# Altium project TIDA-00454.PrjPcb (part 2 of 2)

## Sheet Pg8. Analog Outputs.SchDoc
size 431 x 279 mm; Date: Not shown in title block; ApprovedBy: Not shown in title block; CheckedBy: Not shown in title block; Author: Not shown in title block; CompanyName: Not shown in title block; Engineer: Not shown in title block; Organization: Not shown in title block; Address1: Not shown in title block; Address2: Not shown in title block; Address3: Not shown in title block; Address4: Not shown in title block; DocumentNumber: 7; Revision: Use project parameter SCH_Rev; SheetNumber: 8; SheetTotal: 10; PageSetup: Record=PageOptions¦CenterHorizontal=True¦CenterVertical=True¦PrintScale=1.00¦XCorrection=1.00¦YCorrection=1.00¦PrintKind=0¦BorderSize=5000000¦LeftOffset=0¦BottomOffset=0¦Orientation=2¦PaperLength=1000¦PaperWidth=1000¦Scale=100¦PaperSource=15¦PrintQuality=600¦MediaType=1¦DitherType=10¦PaperKind=Letter¦PrintScaleMode=1
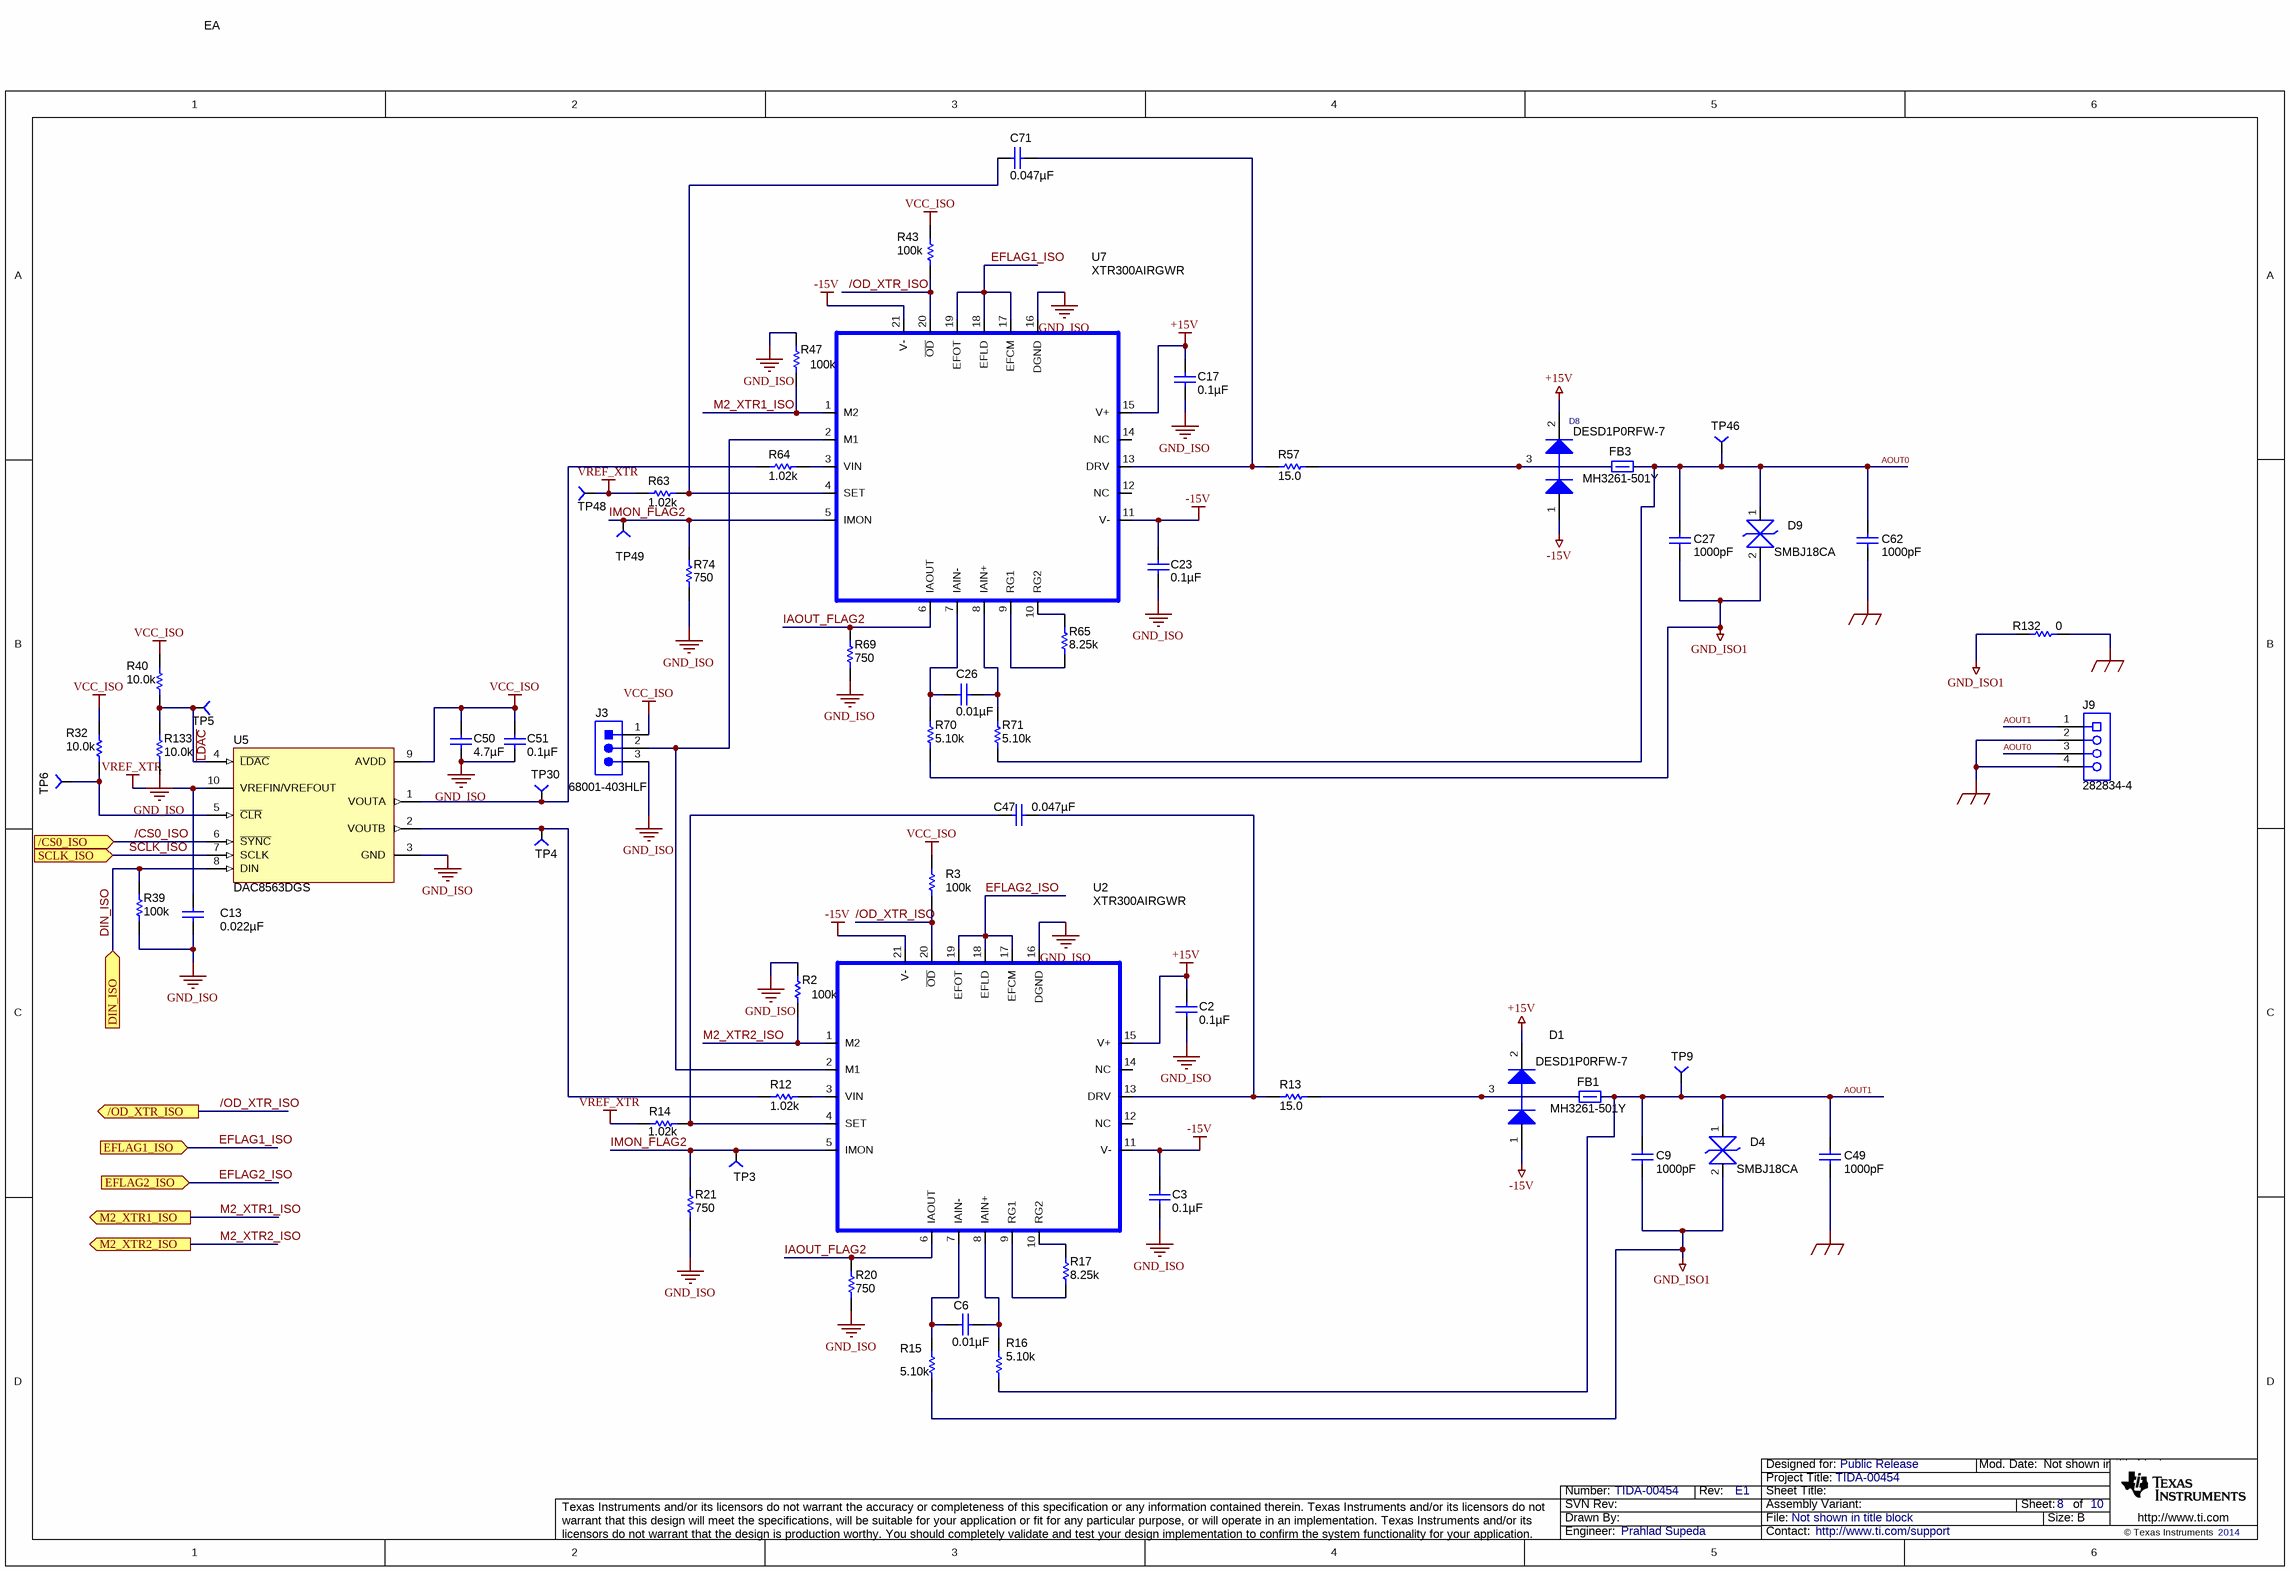
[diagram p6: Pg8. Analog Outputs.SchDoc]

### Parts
C2  ValueDisplayed: 0.1µF  [0603]  (hidden comment: GRM188R71H104KA93D)
C3  ValueDisplayed: 0.1µF  [0603]  (hidden comment: GRM188R71H104KA93D)
C6  ValueDisplayed: 0.01µF  [0603]  (hidden comment: C0603C103J5RACTU)
C9  value 1000pF  [1206]  (hidden comment: 202R18W102KV4E)
C13  ValueDisplayed: 0.022µF  [0603]  (hidden comment: C0603C223K4RACTU)
C17  ValueDisplayed: 0.1µF  [0603]  (hidden comment: GRM188R71H104KA93D)
C23  ValueDisplayed: 0.1µF  [0603]  (hidden comment: GRM188R71H104KA93D)
C26  ValueDisplayed: 0.01µF  [0603]  (hidden comment: C0603C103J5RACTU)
C27  value 1000pF  [1206]  (hidden comment: 202R18W102KV4E)
C47  ValueDisplayed: 0.047µF  [0603]  (hidden comment: C1608X7R1H473K)
C49  value 1000pF  [1206]  (hidden comment: 202R18W102KV4E)
C50  ValueDisplayed: 4.7µF  [1206]  (hidden comment: C3216X7R1C475K)
C51  ValueDisplayed: 0.1µF  [0603]  (hidden comment: GRM188R71H104KA93D)
C62  value 1000pF  [1206]  (hidden comment: 202R18W102KV4E)
C71  ValueDisplayed: 0.047µF  [0603]  (hidden comment: C1608X7R1H473K)
D1  DESD1P0RFW-7  [SOT-323]
D4  SMBJ18CA  [DIO_SMB_BIAAAA]
D8  DESD1P0RFW-7  [SOT-323]
D9  SMBJ18CA  [DIO_SMB_BIAAAA]
FB1  MH3261-501Y  [1210]
FB3  MH3261-501Y  [1210]
J3  68001-403HLF  [HDR1X3]
J9  282834-4  [TEC_282834-4]
R2  value 100k  [0603]  (hidden comment: CRCW0603100KFKEA)
R3  value 100k  [0603]  (hidden comment: CRCW0603100KFKEA)
R12  value 1.02k  [0603]  (hidden comment: RT0603BRD071K02L)
R13  value 15.0  [0603]  (hidden comment: CRCW060315R0FKEA)
R14  value 1.02k  [0603]  (hidden comment: RT0603BRD071K02L)
R15  value 5.10k  [0603]  (hidden comment: CRCW06032K00FKEA)
R16  value 5.10k  [0603]  (hidden comment: CRCW06032K00FKEA)
R17  value 8.25k  [0603]  (hidden comment: RG1608P-8251-B-T5)
R20  value 750  [0603]  (hidden comment: CRCW0603750RFKEA)
R21  value 750  [0603]  (hidden comment: CRCW0603750RFKEA)
R32  value 10.0k  [0603]  (hidden comment: CRCW060310K0FKEA)
R39  value 100k  [0603]  (hidden comment: CRCW0603100KFKEA)
R40  value 10.0k  [0603]  (hidden comment: CRCW060310K0FKEA)
R43  value 100k  [0603]  (hidden comment: CRCW0603100KFKEA)
R47  value 100k  [0603]  (hidden comment: CRCW0603100KFKEA)
R57  value 15.0  [0603]  (hidden comment: CRCW060315R0FKEA)
R63  value 1.02k  [0603]  (hidden comment: RT0603BRD071K02L)
R64  value 1.02k  [0603]  (hidden comment: RT0603BRD071K02L)
R65  value 8.25k  [0603]  (hidden comment: RG1608P-8251-B-T5)
R69  value 750  [0603]  (hidden comment: CRCW0603750RFKEA)
R70  value 5.10k  [0603]  (hidden comment: CRCW06032K00FKEA)
R71  value 5.10k  [0603]  (hidden comment: CRCW06032K00FKEA)
R74  value 750  [0603]  (hidden comment: CRCW0603750RFKEA)
R132  value 0  [0603]  (hidden comment: RC0603JR-070RL)
R133  value 10.0k  [0603]  (hidden comment: CRCW060310K0FKEA)
TP3  TP-040_RND  [TP-040_RND]  (value not drawn)
TP4  TP-040_RND  [TP-040_RND]  (value not drawn)
TP5  TP-040_RND  [TP-040_RND]  (value not drawn)
TP6  TP-040_RND  [TP-040_RND]  (value not drawn)
TP9  TP-040_RND  [TP-040_RND]  (value not drawn)
TP30  TP-040_RND  [TP-040_RND]  (value not drawn)
TP46  TP-040_RND  [TP-040_RND]  (value not drawn)
TP48  TP-040_RND  [TP-040_RND]  (value not drawn)
TP49  TP-040_RND  [TP-040_RND]  (value not drawn)
U2  XTR300AIRGWR  [RGW20]
U5  DAC8563DGS  U/M: EA  [DGS0010A_N]
U7  XTR300AIRGWR  [RGW20]

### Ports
/CS0_ISO (in), /OD_XTR_ISO (out), DIN_ISO (in), EFLAG1_ISO (in), EFLAG2_ISO (in), M2_XTR1_ISO (out), M2_XTR2_ISO (out), SCLK_ISO (in)

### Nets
+15V: C2.1 C17.1 D1.2(K) D8.2(K) U2.15(V+) U7.15(V+)
-15V: C3.1 C23.1 D1.1(A) D8.1(A) U2.11(V-) U2.21(V-) U7.11(V-) U7.21(V-)
GND_EARTH: C49.2 C62.2 J9.2 J9.4 R132.2
GND_ISO: C2.2 C3.2 C13.2 C17.2 C23.2 C50.2 C51.2 J3.3 R2.2 R20.2 R21.1 R39.1 R47.2 R69.2 R74.1 R133.1 U2.16(DGND) U5.3(GND) U7.16(DGND)
GND_ISO1: C9.2 C27.2 D4.2 D9.2 R15.1 R70.1 R132.1
VCC_ISO: C50.1 C51.1 J3.1 R3.2 R32.2 R40.2 R43.2 U5.9(AVDD)
VREF_XTR: C13.1 R14.1 R63.1 TP48.1 U5.10(VREFIN/VREFOUT)
/CS0_ISO: U5.6(~{SYNC}) ; port /CS0_ISO
/OD_XTR_ISO: R3.1 R43.1 U2.20(~{OD}) U7.20(~{OD}) ; port /OD_XTR_ISO
~{LDAC}: R40.1 R133.2 TP5.1 U5.4(~{LDAC})
AOUT0: C27.1 C62.1 D9.1 FB3.2 J9.3 R71.1 TP46.1
AOUT1: C9.1 C49.1 D4.1 FB1.2 J9.1 R16.1 TP9.1
DIN_ISO: R39.2 U5.8(DIN) ; port DIN_ISO
EFLAG1_ISO: U7.17(EFCM) U7.18(EFLD) U7.19(EFOT) ; port EFLAG1_ISO
EFLAG2_ISO: U2.17(EFCM) U2.18(EFLD) U2.19(EFOT) ; port EFLAG2_ISO
IAOUT_FLAG2: R20.1 R69.1 U2.6(IAOUT) U7.6(IAOUT)
IMON_FLAG2: R21.2 R74.2 TP3.1 TP49.1 U2.5(IMON) U7.5(IMON)
M2_XTR1_ISO: R47.1 U7.1(M2) ; port M2_XTR1_ISO
M2_XTR2_ISO: R2.1 U2.1(M2) ; port M2_XTR2_ISO
SCLK_ISO: U5.7(SCLK) ; port SCLK_ISO
NetC6_1: C6.1 R16.2 U2.8(IAIN+)
NetC6_2: C6.2 R15.2 U2.7(IAIN-)
NetC26_1: C26.1 R71.2 U7.8(IAIN+)
NetC26_2: C26.2 R70.2 U7.7(IAIN-)
NetC47_1: C47.1 R13.1 U2.13(DRV)
NetC47_2: C47.2 R14.2 U2.4(SET)
NetC71_1: C71.1 R57.1 U7.13(DRV)
NetC71_2: C71.2 R63.2 U7.4(SET)
NetD1_3: D1.3(C) FB1.1 R13.2
NetD8_3: D8.3(C) FB3.1 R57.2
NetJ3_2: J3.2 U2.2(M1) U7.2(M1)
NetR12_1: R12.1 TP4.1 U5.2(VOUTB)
NetR12_2: R12.2 U2.3(VIN)
NetR17_1: R17.1 U2.9(RG1)
NetR17_2: R17.2 U2.10(RG2)
NetR32_1: R32.1 TP6.1 U5.5(~{CLR})
NetR64_1: R64.1 TP30.1 U5.1(VOUTA)
NetR64_2: R64.2 U7.3(VIN)
NetR65_1: R65.1 U7.9(RG1)
NetR65_2: R65.2 U7.10(RG2)

Not connected (* = marked no-connect by the designer): U2 12(NC) 14(NC); U7 12(NC) 14(NC)

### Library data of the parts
C2 C3 C17 C23 C51 = GRM188R71H104KA93D: CAP, CERM, 0.1uF, 50V, +/-10%, X7R, 0603; Manufacturer: MuRata; Polarized: N; CompType: Capacitor; U/M: EA; Cap_F: 0.0000001; Tolerance_%: 10; VDC_V: 50; TaMin_C: -55; TaMax_C: 125
C6 C26 = C0603C103J5RACTU: CAP, CERM, 0.01uF, 50V, +/-5%, X7R, 0603; Manufacturer: Kemet; Polarized: N; CompType: Capacitor; U/M: EA; Cap_F: 0.00000001; Tolerance_%: 5; Value1: Unknown; VDC_V: 50; TaMin_C: -55; TaMax_C: 125
C9 C27 C49 C62 = 202R18W102KV4E: CAP, CERM, 1000pF, 2KV 10% X7R 1206; Manufacturer: Johanson Dielectrics Inc; Polarized: N; CompType: Capacitor; Cap_F: 0.000000001; Tolerance_%: 0
C13 = C0603C223K4RACTU: CAP, CERM, 0.022uF, 16V, +/-10%, X7R, 0603; Manufacturer: Kemet; Polarized: N; CompType: Capacitor; U/M: EA; Cap_F: 0.000000022; Tolerance_%: 10; Value1: Unknown; VDC_V: 16; TaMin_C: -55; TaMax_C: 125
C47 C71 = C1608X7R1H473K: CAP, CERM, 0.047uF, 50V, +/-10%, X7R, 0603; Manufacturer: TDK; Polarized: N; CompType: Capacitor; U/M: EA; Cap_F: 0.000000047; Tolerance_%: 10; ESR_Ohm: 0.0234; Value1: 0.0234 ohm; VDC_V: 50; TaMin_C: -55; TaMax_C: 125
C50 = C3216X7R1C475K: CAP, CERM, 4.7uF, 16V, +/-10%, X7R, 1206; Manufacturer: TDK; Polarized: N; CompType: Capacitor; U/M: EA; Cap_F: 0.0000047; Tolerance_%: 10; ESR_Ohm: 0.0036; Value1: 0.0036 ohm; VDC_V: 16; IRMS_A: 2; TaMin_C: -55; TaMax_C: 125
D1 D8 = BAV99WT1G: Diode, P-N, 70V, 0.2A, SOT-323; Manufacturer: Diodes Inc
D4 D9 = SMBJ18CA: TVS 18 VOLT 600 WATT BI-DIR SMB; Manufacturer: Littelfuse Inc
FB1 FB3 = Ferrite_Bead: BEAD FERRITE 500 OHM 3.0A 3216; Manufacturer: Bourns Inc.; CompType: Resistor; U/M: EA
J3 = 009155003301006: 3 pin berger; Manufacturer: FCI; SymbolCreator: a0799628; CompType: Connector; U/M: EA
J9 = 282834-4: Receptacle, 100mil, 4X1 TH; Manufacturer: TE Connectivity; SymbolCreator: a0411947; U/M: EA
R2 R3 R39 R43 R47 = CRCW0603100KFKEA: RES, 100k ohm, 1%, 0.1W, 0603; Manufacturer: Vishay-Dale; CompType: Resistor; Res_ohm: 100000; Tolerance_%: 1; Power_W: 0.1; VDC_V: 75; TempCo: 100 ppm/C; EIA_Code: E96; U/M: EA
R12 R14 R63 R64 = RT0603BRD071K02L: RES, 1.02k ohm, 0.1%, 0.1W, 0603; Manufacturer: Yageo America; CompType: Resistor; Res_ohm: 1020; Value_Code: 1k02; Tolerance_%: 0.1; VDC_V: 75; TempCo: 25 ppm/C; EIA_Code: E192; U/M: EA
R13 R57 = CRCW080515R0FKEA: RES, 15.0 ohm, 1%, 0.125W, 0805; Manufacturer: Vishay-Dale; CompType: Resistor; Res_ohm: 15; Value_Code: 15R0; Tolerance_%: 1; Power_W: 0.125; VDC_V: 150; TempCo: 100 ppm/C; EIA_Code: E96; U/M: EA
R15 R16 R70 R71 = RC0603FR-075K1L: RES, 5.10k ohm, 1%, 0.1W, 0603; Manufacturer: Yageo America; CompType: Resistor; Res_ohm: 5100; Value_Code: 5k10; Tolerance_%: 1; Power_W: 0.1; VDC_V: 150; TempCo: 200 ppm/C; U/M: EA
R17 R65 = RG1608P-8251-B-T5: RES, 8.25k ohm, 0.1%, 0.1W, 0603; Manufacturer: Susumu Co Ltd; CompType: Resistor; Res_ohm: 8250; Value_Code: 8k25; Tolerance_%: 0.1; VDC_V: 75; TempCo: 25 ppm/C; EIA_Code: E192; U/M: EA
R20 R21 R69 R74 = CRCW0603750RFKEA: RES, 750 ohm, 1%, 0.1W, 0603; Manufacturer: Vishay-Dale; CompType: Resistor; Value_Code: 750R; Tolerance_%: 1; Power_W: 0.1; VDC_V: 75; TempCo: 100 ppm/C; EIA_Code: E96; U/M: EA
R32 R40 R133 = CRCW060310K0FKEA: RES, 10.0k ohm, 1%, 0.1W, 0603; Manufacturer: Vishay-Dale; CompType: Resistor; Res_ohm: 10000; Value_Code: 10k0; Tolerance_%: 1; Power_W: 0.1; VDC_V: 75; TempCo: 100 ppm/C; EIA_Code: E96; U/M: EA
R132 = RC0402JR-070RL: RES, 0 ohm,5%, 0.1W, 0603; Manufacturer: Yageo America; CompType: Resistor; Value_Code: 0000; Tolerance_%: 5; Power_W: 0.1; VDC_V: 50; TempCo: 200 ppm/C; EIA_Code: E24; U/M: EA
TP3-TP6 TP9 TP30 TP46 TP48 TP49 = TP-040_RND: Test Point, O.040 Hole; Manufacturer: STD; Value: STD
U2 U7 = XTR300AIRGWR: IC, Industrial Analog Current/Voltage Output Driver; Area: 72900; Note: Please confirm to Librarian when the part is officially released
U5 = DAC8563DGS: DUAL 16-/14-/12-BIT, ULTRALOW-GLITCH, LOW-POWER, BUFFERED, VOLTAGE-OUTPUT DAC WITH 2.5-V, 4-PPM/°C INTERNAL REFERENCE IN SMALL 3-MM ?3-MM SON, DGS0010A; Alternate Manufacturer: None; Manufacturer: Texas Instruments; SymbolCreator: a0411947; CompType: IC

## Sheet Pg9 Expansion Interface.SchDoc
size 431 x 279 mm; Date: Not shown in title block; ApprovedBy: Not shown in title block; CheckedBy: Not shown in title block; Author: Not shown in title block; CompanyName: Not shown in title block; Engineer: Not shown in title block; Organization: Not shown in title block; Address1: Not shown in title block; Address2: Not shown in title block; Address3: Not shown in title block; Address4: Not shown in title block; DocumentNumber: 7; Revision: Use project parameter SCH_Rev; SheetNumber: 9; SheetTotal: 10; PageSetup: Record=PageOptions¦CenterHorizontal=True¦CenterVertical=True¦PrintScale=1.00¦XCorrection=1.00¦YCorrection=1.00¦PrintKind=0¦BorderSize=5000000¦LeftOffset=0¦BottomOffset=0¦Orientation=2¦PaperLength=1000¦PaperWidth=1000¦Scale=100¦PaperSource=15¦PrintQuality=600¦MediaType=1¦DitherType=10¦PaperKind=Letter¦PrintScaleMode=1
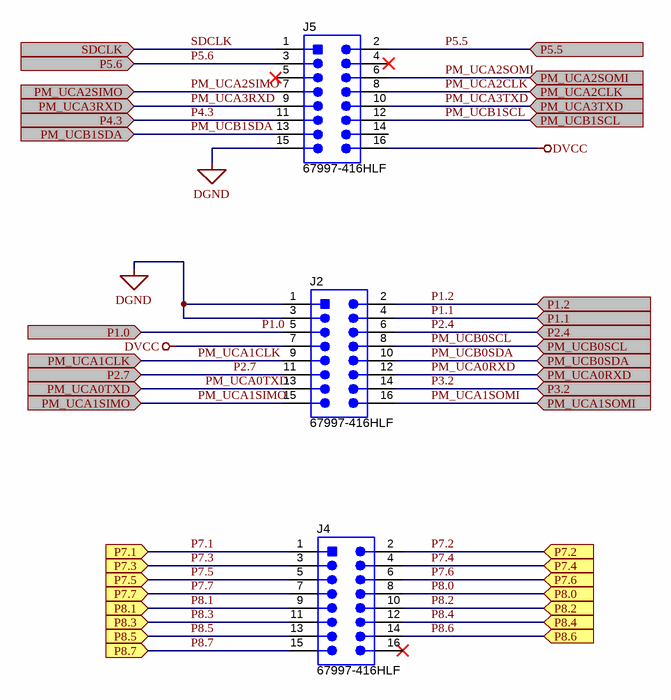
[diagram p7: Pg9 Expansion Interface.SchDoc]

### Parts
J2  67997-416HLF  [TSW-108-07-G-D]
J4  67997-416HLF  [TSW-108-07-G-D]
J5  67997-416HLF  [TSW-108-07-G-D]

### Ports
P1.0, P1.1, P1.2, P2.4, P2.7, P3.2, P4.3, P5.5, P5.6, P7.1, P7.2, P7.3, P7.4, P7.5, P7.6, P7.7, P8.0, P8.1, P8.2, P8.3, P8.4, P8.5, P8.6, P8.7, PM_UCA0RXD, PM_UCA0TXD, PM_UCA1CLK, PM_UCA1SIMO, PM_UCA1SOMI, PM_UCA2CLK, PM_UCA2SIMO, PM_UCA2SOMI, PM_UCA3RXD, PM_UCA3TXD, PM_UCB0SCL, PM_UCB0SDA, PM_UCB1SCL, PM_UCB1SDA, SDCLK

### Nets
DGND: J2.1 J2.3 J5.15
DVCC: J2.7 J5.16
P1.0: J2.5 ; port P1.0
P1.1: J2.4 ; port P1.1
P1.2: J2.2 ; port P1.2
P2.4: J2.6 ; port P2.4
P2.7: J2.11 ; port P2.7
P3.2: J2.14 ; port P3.2
P4.3: J5.11 ; port P4.3
P5.5: J5.2 ; port P5.5
P5.6: J5.3 ; port P5.6
P7.1: J4.1 ; port P7.1
P7.2: J4.2 ; port P7.2
P7.3: J4.3 ; port P7.3
P7.4: J4.4 ; port P7.4
P7.5: J4.5 ; port P7.5
P7.6: J4.6 ; port P7.6
P7.7: J4.7 ; port P7.7
P8.0: J4.8 ; port P8.0
P8.1: J4.9 ; port P8.1
P8.2: J4.10 ; port P8.2
P8.3: J4.11 ; port P8.3
P8.4: J4.12 ; port P8.4
P8.5: J4.13 ; port P8.5
P8.6: J4.14 ; port P8.6
P8.7: J4.15 ; port P8.7
PM_UCA0RXD: J2.12 ; port PM_UCA0RXD
PM_UCA0TXD: J2.13 ; port PM_UCA0TXD
PM_UCA1CLK: J2.9 ; port PM_UCA1CLK
PM_UCA1SIMO: J2.15 ; port PM_UCA1SIMO
PM_UCA1SOMI: J2.16 ; port PM_UCA1SOMI
PM_UCA2CLK: J5.8 ; port PM_UCA2CLK
PM_UCA2SIMO: J5.7 ; port PM_UCA2SIMO
PM_UCA2SOMI: J5.6 ; port PM_UCA2SOMI
PM_UCA3RXD: J5.9 ; port PM_UCA3RXD
PM_UCA3TXD: J5.10 ; port PM_UCA3TXD
PM_UCB0SCL: J2.8 ; port PM_UCB0SCL
PM_UCB0SDA: J2.10 ; port PM_UCB0SDA
PM_UCB1SCL: J5.12 ; port PM_UCB1SCL
PM_UCB1SDA: J5.13 ; port PM_UCB1SDA
SDCLK: J5.1 ; port SDCLK

Not connected (* = marked no-connect by the designer): J4 16*; J5 4* 5* 14

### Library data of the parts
J2 J4 J5 = PBC08DBAN: Header, 8x2, 100mil, TH; Manufacturer: FCI; SymbolCreator: a0412235; U/M: EA

## Sheet Pg10.HARDWARE - MISCELLANEOUS..SchDoc: Hardware - MIiscellaneous
size 431 x 279 mm; Date: Not shown in title block; ApprovedBy: Not shown in title block; CheckedBy: Not shown in title block; Author: Not shown in title block; CompanyName: Not shown in title block; Engineer: Not shown in title block; Organization: Not shown in title block; Address1: Not shown in title block; Address2: Not shown in title block; Address3: Not shown in title block; Address4: Not shown in title block; DocumentNumber: 8; Revision: Use project parameter SCH_Rev; SheetNumber: 10; SheetTotal: 10; PageSetup: Record=PageOptions¦CenterHorizontal=True¦CenterVertical=True¦PrintScale=1.00¦XCorrection=1.00¦YCorrection=1.00¦PrintKind=0¦BorderSize=5000000¦LeftOffset=0¦BottomOffset=0¦Orientation=2¦PaperLength=1000¦PaperWidth=1000¦Scale=100¦PaperSource=15¦PrintQuality=600¦MediaType=1¦DitherType=10¦PaperKind=Letter¦PrintScaleMode=1
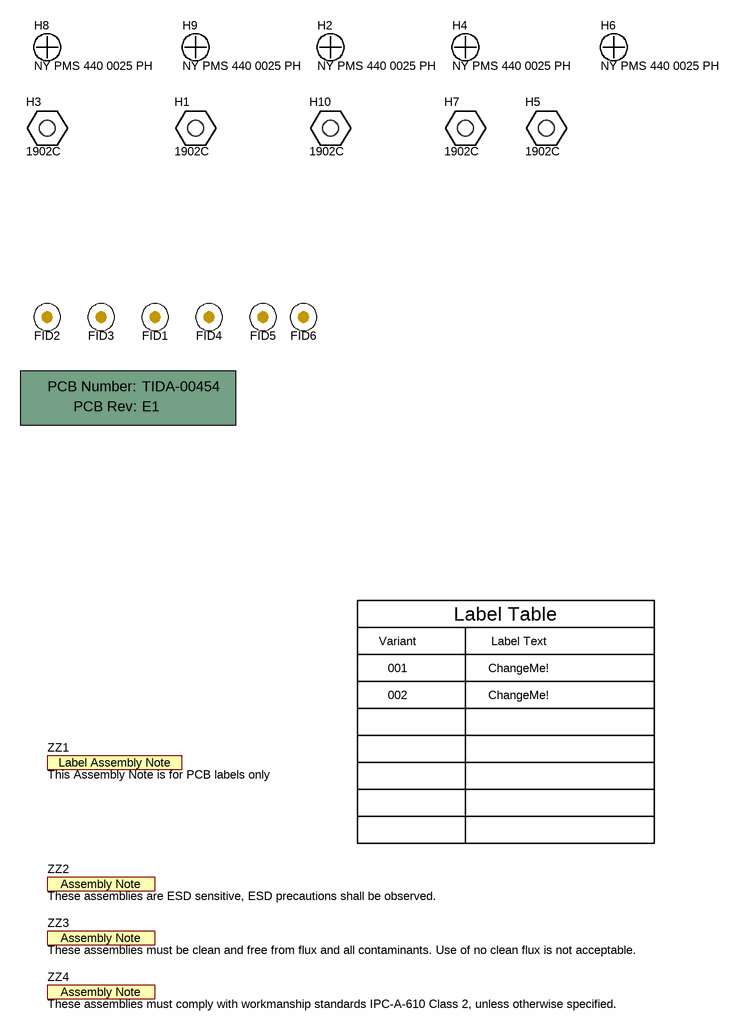
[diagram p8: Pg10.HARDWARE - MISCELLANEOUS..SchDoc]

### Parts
!PCB1  Printed Circuit Board  (value not drawn)  (mechanical)
FID1  Fiducial  [Fiducial10-20]  (value not drawn)
FID2  Fiducial  [Fiducial10-20]  (value not drawn)
FID3  Fiducial  [Fiducial10-20]  (value not drawn)
FID4  Fiducial  [Fiducial10-20]  (value not drawn)
FID5  Fiducial  [Fiducial10-20]  (value not drawn)
FID6  Fiducial  [Fiducial10-20]  (value not drawn)
H1  1902C  [Keystone_1902C]
H2  NY PMS 440 0025 PH  [NY PMS 440 0025 PH]
H3  1902C  [Keystone_1902C]
H4  NY PMS 440 0025 PH  [NY PMS 440 0025 PH]
H5  1902C  [Keystone_1902C]
H6  NY PMS 440 0025 PH  [NY PMS 440 0025 PH]
H7  1902C  [Keystone_1902C]
H8  NY PMS 440 0025 PH  [NY PMS 440 0025 PH]
H9  NY PMS 440 0025 PH  [NY PMS 440 0025 PH]
H10  1902C  [Keystone_1902C]
ZZ1  This Assembly Note is for PCB labels only  [AssemblyNoteLabel]  (no BOM)
ZZ2  These assemblies are ESD sensitive, ESD precautions shall be observed.  [AssemblyNote]  (no BOM)
ZZ3  These assemblies must be clean and free from flux and all contaminants. Use of no clean flux is not acceptable.  [AssemblyNote]  (no BOM)
ZZ4  These assemblies must comply with workmanship standards IPC-A-610 Class 2, unless otherwise specified.  [AssemblyNote]  (no BOM)

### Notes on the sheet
- Variant
- Label Table
- Label Text
- 001
- 002
- ChangeMe!

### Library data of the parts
!PCB1 = PCB: Manufacturer: Any; PartNumber: TIDA-00454; SymbolCreator: a0412235
FID1-FID6 = Fiducial: Fiducial mark.  There is nothing to buy or mount.; SymbolCreator: codlsc
H1 H3 H5 H7 H10 = 1902C: Standoff, Hex, 0.5"L #4-40 Nylon; Manufacturer: Keystone; CompType: Hardware
H2 H4 H6 H8 H9 = NY PMS 440 0025 PH: Machine Screw, Round, #4-40 x 1/4, Nylon, Philips panhead; Manufacturer: B&F Fastener Supply; CompType: Hardware; SymbolCreator: codlsc; U/M: EA
ZZ1 = AssemblyNoteLabel: SymbolCreator: a0412235
ZZ2-ZZ4 = AssemblyNote: SymbolCreator: codlsc

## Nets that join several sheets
+15V: Pg6.Isolated and Non Isolated Power Supply (9 pins), Pg8. Analog Outputs (6 pins)
-15V: Pg6.Isolated and Non Isolated Power Supply (C72.2 C74.2 D12.2 J14.2), Pg8. Analog Outputs (8 pins)
AGND: Pg3.MSP430F67791A+LED (U6.112 U6.120), Pg4. Relay Drivers+JTAG Interface +Decoupling Capacitors (8 pins), Pg5.Analog Front End - Current and Voltage (36 pins)
AVCC: Pg3.MSP430F67791A+LED (U6.121), Pg4. Relay Drivers+JTAG Interface +Decoupling Capacitors (C68.1 C69.1 FB4.2)
DGND: Pg3.MSP430F67791A+LED (14 pins), Pg4. Relay Drivers+JTAG Interface +Decoupling Capacitors (21 pins), Pg6.Isolated and Non Isolated Power Supply (10 pins), Pg7.Digital Isolators (7 pins), Pg9 Expansion Interface (J2.1 J2.3 J5.15)
DVCC: Pg3.MSP430F67791A+LED (7 pins), Pg4. Relay Drivers+JTAG Interface +Decoupling Capacitors (9 pins), Pg6.Isolated and Non Isolated Power Supply (5 pins), Pg7.Digital Isolators (16 pins), Pg9 Expansion Interface (J2.7 J5.16)
GND_ISO: Pg6.Isolated and Non Isolated Power Supply (17 pins), Pg7.Digital Isolators (7 pins), Pg8. Analog Outputs (19 pins)
GND_ISO1: Pg6.Isolated and Non Isolated Power Supply (R106.1 R107.1), Pg8. Analog Outputs (7 pins)
VASYS1: Pg3.MSP430F67791A+LED (U6.111 U6.122), Pg4. Relay Drivers+JTAG Interface +Decoupling Capacitors (C63.1 C65.1 C67.1 C70.1)
VCC_ISO: Pg6.Isolated and Non Isolated Power Supply (6 pins), Pg7.Digital Isolators (14 pins), Pg8. Analog Outputs (8 pins)
VREF: Pg3.MSP430F67791A+LED (U6.113), Pg4. Relay Drivers+JTAG Interface +Decoupling Capacitors (C64.1)
/CS0: Pg3.MSP430F67791A+LED (U6.35), Pg7.Digital Isolators (R22.1 U4.3)
/CS0_ISO: Pg7.Digital Isolators (R23.2 R37.1), Pg8. Analog Outputs (U5.6)
/OD_XTR: Pg3.MSP430F67791A+LED (U6.34), Pg7.Digital Isolators (R52.1 R53.2 U8.5)
/OD_XTR_ISO: Pg7.Digital Isolators (R56.1 R62.2), Pg8. Analog Outputs (R3.1 R43.1 U2.20 U7.20)
AUXVCC1: Pg3.MSP430F67791A+LED (U6.124), Pg4. Relay Drivers+JTAG Interface +Decoupling Capacitors (C54.1 C55.1 TP53.1)
AUXVCC2: Pg3.MSP430F67791A+LED (U6.123), Pg4. Relay Drivers+JTAG Interface +Decoupling Capacitors (C52.1 C53.1)
AUXVCC3: Pg3.MSP430F67791A+LED (R108.2 U6.3), Pg4. Relay Drivers+JTAG Interface +Decoupling Capacitors (C59.1 C60.1 TP52.1)
DIN_ISO: Pg7.Digital Isolators (R29.2 R30.1 R38.2), Pg8. Analog Outputs (R39.2 U5.8)
EFLAG1: Pg3.MSP430F67791A+LED (TP7.1 U6.26), Pg7.Digital Isolators (R27.1 U4.6)
EFLAG1_ISO: Pg7.Digital Isolators (R31.1 R50.2), Pg8. Analog Outputs (U7.17 U7.18 U7.19)
EFLAG2: Pg3.MSP430F67791A+LED (TP17.1 U6.27), Pg7.Digital Isolators (R60.1 U8.6)
EFLAG2_ISO: Pg7.Digital Isolators (R61.1 R67.2), Pg8. Analog Outputs (U2.17 U2.18 U2.19)
I1+: Pg3.MSP430F67791A+LED (U6.103), Pg5.Analog Front End - Current and Voltage (C18.1 C21.1 R51.1)
I1-: Pg3.MSP430F67791A+LED (U6.104), Pg5.Analog Front End - Current and Voltage (C21.2 C24.2 R66.1)
I2+: Pg3.MSP430F67791A+LED (U6.105), Pg5.Analog Front End - Current and Voltage (C28.1 C33.1 R75.1)
I2-: Pg3.MSP430F67791A+LED (U6.106), Pg5.Analog Front End - Current and Voltage (C28.2 C34.2 R76.1)
I3+: Pg3.MSP430F67791A+LED (U6.107), Pg5.Analog Front End - Current and Voltage (C29.1 C35.1 R77.1)
I3-: Pg3.MSP430F67791A+LED (U6.108), Pg5.Analog Front End - Current and Voltage (C29.2 C36.2 R78.1)
M2_XTR1: Pg3.MSP430F67791A+LED (U6.28), Pg7.Digital Isolators (R45.1 U8.3)
M2_XTR1_ISO: Pg7.Digital Isolators (R54.2 R68.1), Pg8. Analog Outputs (R47.1 U7.1)
M2_XTR2: Pg3.MSP430F67791A+LED (U6.29), Pg7.Digital Isolators (R48.1 U8.4)
M2_XTR2_ISO: Pg7.Digital Isolators (R49.1 R55.2), Pg8. Analog Outputs (R2.1 U2.1)
P1.0: Pg3.MSP430F67791A+LED (U6.11), Pg9 Expansion Interface (J2.5)
P1.1: Pg3.MSP430F67791A+LED (U6.10), Pg9 Expansion Interface (J2.4)
P1.2: Pg3.MSP430F67791A+LED (U6.9), Pg9 Expansion Interface (J2.2)
P2.4: Pg3.MSP430F67791A+LED (U6.12), Pg9 Expansion Interface (J2.6)
P2.7: Pg3.MSP430F67791A+LED (U6.15), Pg9 Expansion Interface (J2.11)
P3.2: Pg3.MSP430F67791A+LED (U6.18), Pg9 Expansion Interface (J2.14)
P4.3: Pg3.MSP430F67791A+LED (U6.41), Pg9 Expansion Interface (J5.11)
P5.5: Pg3.MSP430F67791A+LED (R100.1 R101.1 U6.32), Pg9 Expansion Interface (J5.2)
P5.6: Pg3.MSP430F67791A+LED (U6.33), Pg9 Expansion Interface (J5.3)
P7.1: Pg3.MSP430F67791A+LED (U6.54), Pg9 Expansion Interface (J4.1)
P7.2: Pg3.MSP430F67791A+LED (U6.55), Pg9 Expansion Interface (J4.2)
P7.3: Pg3.MSP430F67791A+LED (U6.56), Pg9 Expansion Interface (J4.3)
P7.4: Pg3.MSP430F67791A+LED (U6.57), Pg9 Expansion Interface (J4.4)
P7.5: Pg3.MSP430F67791A+LED (U6.58), Pg9 Expansion Interface (J4.5)
P7.6: Pg3.MSP430F67791A+LED (U6.59), Pg9 Expansion Interface (J4.6)
P7.7: Pg3.MSP430F67791A+LED (U6.60), Pg9 Expansion Interface (J4.7)
P8.0: Pg3.MSP430F67791A+LED (U6.61), Pg9 Expansion Interface (J4.8)
P8.1: Pg3.MSP430F67791A+LED (U6.62), Pg9 Expansion Interface (J4.9)
P8.2: Pg3.MSP430F67791A+LED (U6.63), Pg9 Expansion Interface (J4.10)
P8.3: Pg3.MSP430F67791A+LED (U6.64), Pg9 Expansion Interface (J4.11)
P8.4: Pg3.MSP430F67791A+LED (U6.65), Pg9 Expansion Interface (J4.12)
P8.5: Pg3.MSP430F67791A+LED (U6.66), Pg9 Expansion Interface (J4.13)
P8.6: Pg3.MSP430F67791A+LED (U6.67), Pg9 Expansion Interface (J4.14)
P8.7: Pg3.MSP430F67791A+LED (U6.68), Pg9 Expansion Interface (J4.15)
PM_UCA0RXD: Pg3.MSP430F67791A+LED (U6.16), Pg9 Expansion Interface (J2.12)
PM_UCA0TXD: Pg3.MSP430F67791A+LED (U6.17), Pg9 Expansion Interface (J2.13)
PM_UCA1CLK: Pg3.MSP430F67791A+LED (U6.19), Pg9 Expansion Interface (J2.9)
PM_UCA1SIMO: Pg3.MSP430F67791A+LED (U6.21), Pg9 Expansion Interface (J2.15)
PM_UCA1SOMI: Pg3.MSP430F67791A+LED (U6.20), Pg9 Expansion Interface (J2.16)
PM_UCA2CLK: Pg3.MSP430F67791A+LED (U6.38), Pg7.Digital Isolators (R24.1 U4.4), Pg9 Expansion Interface (J5.8)
PM_UCA2SIMO: Pg3.MSP430F67791A+LED (U6.37), Pg7.Digital Isolators (R28.1 U4.5), Pg9 Expansion Interface (J5.7)
PM_UCA2SOMI: Pg3.MSP430F67791A+LED (U6.36), Pg9 Expansion Interface (J5.6)
PM_UCA3RXD: Pg3.MSP430F67791A+LED (U6.39), Pg9 Expansion Interface (J5.9)
PM_UCA3TXD: Pg3.MSP430F67791A+LED (U6.40), Pg9 Expansion Interface (J5.10)
PM_UCB0SCL: Pg3.MSP430F67791A+LED (R104.1 U6.13), Pg9 Expansion Interface (J2.8)
PM_UCB0SDA: Pg3.MSP430F67791A+LED (R105.1 U6.14), Pg9 Expansion Interface (J2.10)
PM_UCB1SCL: Pg3.MSP430F67791A+LED (R99.1 U6.42), Pg9 Expansion Interface (J5.12)
PM_UCB1SDA: Pg3.MSP430F67791A+LED (R98.1 U6.43), Pg9 Expansion Interface (J5.13)
RELAY_1: Pg3.MSP430F67791A+LED (U6.53), Pg4. Relay Drivers+JTAG Interface +Decoupling Capacitors (R6.1)
RELAY_2: Pg3.MSP430F67791A+LED (U6.52), Pg4. Relay Drivers+JTAG Interface +Decoupling Capacitors (R5.1)
RELAY_3: Pg3.MSP430F67791A+LED (U6.51), Pg4. Relay Drivers+JTAG Interface +Decoupling Capacitors (R7.1)
RELAY_4: Pg3.MSP430F67791A+LED (U6.50), Pg4. Relay Drivers+JTAG Interface +Decoupling Capacitors (R8.1)
RELAY_5: Pg3.MSP430F67791A+LED (U6.49), Pg4. Relay Drivers+JTAG Interface +Decoupling Capacitors (R11.1)
RELAY_6: Pg3.MSP430F67791A+LED (U6.48), Pg4. Relay Drivers+JTAG Interface +Decoupling Capacitors (R9.1)
RESET: Pg3.MSP430F67791A+LED (U6.102), Pg4. Relay Drivers+JTAG Interface +Decoupling Capacitors (5 pins)
SCLK_ISO: Pg7.Digital Isolators (R25.2 R46.1), Pg8. Analog Outputs (U5.7)
SDCLK: Pg3.MSP430F67791A+LED (R101.2 R103.1 U6.31), Pg9 Expansion Interface (J5.1)
TCK: Pg3.MSP430F67791A+LED (U6.101), Pg4. Relay Drivers+JTAG Interface +Decoupling Capacitors (J10.7 R42.2)
TDI: Pg3.MSP430F67791A+LED (U6.99), Pg4. Relay Drivers+JTAG Interface +Decoupling Capacitors (J10.3 R34.2)
TDO: Pg3.MSP430F67791A+LED (U6.98), Pg4. Relay Drivers+JTAG Interface +Decoupling Capacitors (J10.1 R26.2)
TEST/SBWTCK: Pg3.MSP430F67791A+LED (U6.97), Pg4. Relay Drivers+JTAG Interface +Decoupling Capacitors (J10.8)
TMS: Pg3.MSP430F67791A+LED (U6.100), Pg4. Relay Drivers+JTAG Interface +Decoupling Capacitors (J10.5 R41.2)
V1+: Pg3.MSP430F67791A+LED (U6.109), Pg5.Analog Front End - Current and Voltage (C30.1 C37.1 R79.1)
V1-: Pg3.MSP430F67791A+LED (U6.110), Pg5.Analog Front End - Current and Voltage (C30.2 C38.2 R80.1)
V2+: Pg3.MSP430F67791A+LED (U6.114), Pg5.Analog Front End - Current and Voltage (C31.1 C39.1 R81.1)
V2-: Pg3.MSP430F67791A+LED (U6.115), Pg5.Analog Front End - Current and Voltage (C31.2 C40.2 R82.1)
V3+: Pg3.MSP430F67791A+LED (U6.116), Pg5.Analog Front End - Current and Voltage (C32.1 C41.1 R83.1)
V3-: Pg3.MSP430F67791A+LED (U6.117), Pg5.Analog Front End - Current and Voltage (C32.2 C42.2 R84.1)
VCORE: Pg3.MSP430F67791A+LED (U6.128), Pg4. Relay Drivers+JTAG Interface +Decoupling Capacitors (C56.1)
VDSYS1: Pg3.MSP430F67791A+LED (C66.2 R108.1 U6.69 U6.125), Pg4. Relay Drivers+JTAG Interface +Decoupling Capacitors (C48.1 C61.1)

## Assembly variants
001: not fitted C16 C22 C52 C55 R22 R24 R27 R28 R30 R31 R37 R40 R45 R46 R48 R49 R52 R56 R59 R60 R61 R68 R85 R86 R87 R88 R89 R100 R101 R103 Y1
